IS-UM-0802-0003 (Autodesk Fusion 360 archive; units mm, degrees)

design "IS-UM-0802-0003" references "3M Screw", "6 holes POWER", "8 ports ethernet v2", "Digitus_DN-651107_LAN-Switch", "SFP SLOT", "LED"
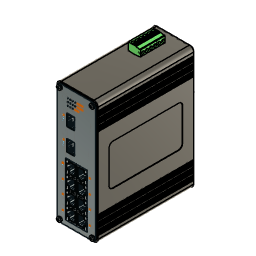
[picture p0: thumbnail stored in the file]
sketch "Sketch1" plane through (0, 0, 0) normal (0, 1, 0) x axis (1, 0, 0)
  line L1 (45, 0) -> (5, 0)
  line L2 (50, -145) -> (50, -5)
  line L3 (5, -150) -> (45, -150)
  line L4 (0, -5) -> (0, -145)
  arc A1 centre (5, -145) radius 5 clockwise from (5, -150) to (0, -145)
  arc A2 centre (45, -145) radius 5 clockwise from (50, -145) to (45, -150)
  arc A3 centre (5, -5) radius 5 clockwise from (0, -5) to (5, 0)
  arc A4 centre (45, -5) radius 5 clockwise from (45, 0) to (50, -5)
  point P1 (0, 0)
  point P2 (0, 0)
  point P4 (0, -150)
  point P3 (50, 0)
  horizontal L1
  vertical L2
  horizontal L3
  vertical L4
  coincident P1 P2
  coincident P4 L3
  coincident P4 L4
  tangent L3 A1
  tangent L4 A1
  tangent L2 A2
  tangent L3 A2
  equal A1 A2
  coincident P2 L1
  coincident P2 L4
  tangent L1 A3
  tangent L4 A3
  equal A1 A3
  coincident P3 L1
  coincident P3 L2
  tangent L1 A4
  tangent L2 A4
  equal A1 A4
  dimension "d1" distance P2 P3 = 50
  dimension "d2" distance P2 P4 = 150
  dimension "d3" radius A1 = 5
extrude "Extrude1" new body sketch "Sketch1" along normal blind 120
sketch "Sketch2" plane through (0, 0, 0) normal (0, -1, 0) x axis (1, 0, 0)
  line L1 (5, 150) -> (45, 150)
  line L2 (0, 5) -> (0, 145)
  line L3 (45, 0) -> (5, 0)
  line L4 (50, 145) -> (50, 5)
  line L5 (45, 1.5) -> (5, 1.5)
  line L6 (48.5, 145) -> (48.5, 5)
  line L7 (5, 148.5) -> (45, 148.5)
  line L8 (1.5, 5) -> (1.5, 145)
  line L9 (45, 0) -> (5, 0)
  line L10 (50, 145) -> (50, 5)
  line L11 (5, 150) -> (45, 150)
  line L12 (0, 5) -> (0, 145)
  arc A1 centre (45, 145) radius 5 clockwise from (45, 150) to (50, 145)
  arc A2 centre (5, 145) radius 5 clockwise from (0, 145) to (5, 150)
  arc A3 centre (5, 5) radius 5 clockwise from (5, 0) to (0, 5)
  arc A4 centre (45, 5) radius 5 clockwise from (50, 5) to (45, 0)
  arc A5 centre (45, 5) radius 3.5 clockwise from (48.5, 5) to (45, 1.5)
  arc A6 centre (45, 145) radius 3.5 clockwise from (45, 148.5) to (48.5, 145)
  arc A7 centre (5, 145) radius 3.5 clockwise from (1.5, 145) to (5, 148.5)
  arc A8 centre (5, 5) radius 3.5 clockwise from (5, 1.5) to (1.5, 5)
  arc A9 centre (45, 5) radius 5 clockwise from (50, 5) to (45, 0)
  arc A10 centre (45, 145) radius 5 clockwise from (45, 150) to (50, 145)
  arc A11 centre (5, 145) radius 5 clockwise from (0, 145) to (5, 150)
  arc A12 centre (5, 5) radius 5 clockwise from (5, 0) to (0, 5)
  dimension "d6" = -1.5
  dimension "d7" distance L3 = 0
extrude "Extrude2" cut sketch "Sketch2" against normal blind 1.5
sketch "Sketch3" plane through (0, 120, 0) normal (0, 1, 0) x axis (-1, 0, 0)
  line L1 (-50, 5) -> (-50, 145)
  line L2 (-5, 0) -> (-45, 0)
  line L3 (0, 145) -> (0, 5)
  line L4 (-45, 150) -> (-5, 150)
  line L5 (-5, 1.5) -> (-45, 1.5)
  line L6 (-1.5, 145) -> (-1.5, 5)
  line L7 (-45, 148.5) -> (-5, 148.5)
  line L8 (-48.5, 5) -> (-48.5, 145)
  line L9 (-5, 0) -> (-45, 0)
  line L10 (0, 145) -> (0, 5)
  line L11 (-45, 150) -> (-5, 150)
  line L12 (-50, 5) -> (-50, 145)
  arc A1 centre (-45, 145) radius 5 clockwise from (-50, 145) to (-45, 150)
  arc A2 centre (-45, 5) radius 5 clockwise from (-45, 0) to (-50, 5)
  arc A3 centre (-5, 5) radius 5 clockwise from (0, 5) to (-5, 0)
  arc A4 centre (-5, 145) radius 5 clockwise from (-5, 150) to (0, 145)
  arc A5 centre (-5, 5) radius 3.5 clockwise from (-1.5, 5) to (-5, 1.5)
  arc A6 centre (-5, 145) radius 3.5 clockwise from (-5, 148.5) to (-1.5, 145)
  arc A7 centre (-45, 145) radius 3.5 clockwise from (-48.5, 145) to (-45, 148.5)
  arc A8 centre (-45, 5) radius 3.5 clockwise from (-45, 1.5) to (-48.5, 5)
  arc A9 centre (-5, 5) radius 5 clockwise from (0, 5) to (-5, 0)
  arc A10 centre (-5, 145) radius 5 clockwise from (-5, 150) to (0, 145)
  arc A11 centre (-45, 145) radius 5 clockwise from (-50, 145) to (-45, 150)
  arc A12 centre (-45, 5) radius 5 clockwise from (-45, 0) to (-50, 5)
  dimension "d10" = -1.5
  dimension "d11" distance L2 = 0
extrude "Extrude3" cut sketch "Sketch3" against normal blind 1.5
sketch "Sketch4" plane through (0, 1.5, 0) normal (0, -1, 0) x axis (1, 0, 0)
  line L1 (1.5, 145) -> (1.5, 5)
  line L2 (45, 148.5) -> (5, 148.5)
  line L3 (48.5, 5) -> (48.5, 145)
  line L4 (5, 1.5) -> (45, 1.5)
  line L5 (45, 0) -> (5, 0)
  line L6 (50, 145) -> (50, 5)
  line L7 (5, 150) -> (45, 150)
  line L8 (0, 5) -> (0, 145)
  line L9 (25, 75) -> (25, 148.5)
  line L10 (25, 75) -> (1.5, 75)
  line L11 (0.75, 9) -> (0, 9)
  line L12 (0.75, 10.5) -> (0.75, 9)
  line L13 (0, 10.5) -> (0.75, 10.5)
  line L14 (0, 9) -> (0, 10.5)
  line L15 (0, 12.75) -> (0.75, 12.75)
  line L16 (0, 11.25) -> (0, 12.75)
  line L17 (0.75, 11.25) -> (0, 11.25)
  line L18 (0.75, 12.75) -> (0.75, 11.25)
  line L19 (0, 15) -> (0.75, 15)
  line L20 (0, 13.5) -> (0, 15)
  line L21 (0.75, 13.5) -> (0, 13.5)
  line L22 (0.75, 15) -> (0.75, 13.5)
  line L23 (0.75, 19.25) -> (0, 19.25)
  line L24 (0.75, 20.75) -> (0.75, 19.25)
  line L25 (0, 19.25) -> (0, 20.75)
  line L26 (0.75, 18.5) -> (0.75, 17)
  line L27 (0, 21.5) -> (0, 23)
  line L28 (0, 23) -> (0.75, 23)
  line L29 (0.75, 21.5) -> (0, 21.5)
  line L30 (0, 20.75) -> (0.75, 20.75)
  line L31 (0, 18.5) -> (0.75, 18.5)
  line L32 (0, 17) -> (0, 18.5)
  line L33 (0.75, 17) -> (0, 17)
  line L34 (0.75, 23) -> (0.75, 21.5)
  line L35 (0.75, 27.25) -> (0, 27.25)
  line L36 (0.75, 28.75) -> (0.75, 27.25)
  line L37 (0, 27.25) -> (0, 28.75)
  line L38 (0.75, 26.5) -> (0.75, 25)
  line L39 (0, 29.5) -> (0, 31)
  line L40 (0, 31) -> (0.75, 31)
  line L41 (0.75, 29.5) -> (0, 29.5)
  line L42 (0, 28.75) -> (0.75, 28.75)
  line L43 (0, 26.5) -> (0.75, 26.5)
  line L44 (0, 25) -> (0, 26.5)
  line L45 (0.75, 25) -> (0, 25)
  line L46 (0.75, 31) -> (0.75, 29.5)
  line L47 (0.75, 141) -> (0, 141)
  line L48 (0, 138.75) -> (0, 137.25)
  line L49 (0, 133) -> (0, 131.5)
  line L50 (0, 120.5) -> (0, 119)
  line L51 (0, 128.5) -> (0, 127)
  line L52 (0, 121.25) -> (0.75, 121.25)
  line L53 (0.75, 125) -> (0, 125)
  line L54 (0.75, 128.5) -> (0, 128.5)
  line L55 (0.75, 129.25) -> (0.75, 130.75)
  line L56 (0.75, 120.5) -> (0, 120.5)
  line L57 (0.75, 131.5) -> (0.75, 133)
  line L58 (0.75, 123.5) -> (0.75, 125)
  line L59 (0, 122.75) -> (0, 121.25)
  line L60 (0.75, 138.75) -> (0, 138.75)
  line L61 (0, 130.75) -> (0, 129.25)
  line L62 (0.75, 130.75) -> (0, 130.75)
  line L63 (0, 139.5) -> (0.75, 139.5)
  line L64 (0.75, 133) -> (0, 133)
  line L65 (0.75, 127) -> (0.75, 128.5)
  line L66 (0.75, 137.25) -> (0.75, 138.75)
  line L67 (0, 137.25) -> (0.75, 137.25)
  line L68 (0.75, 119) -> (0.75, 120.5)
  line L69 (0, 125) -> (0, 123.5)
  line L70 (0.75, 122.75) -> (0, 122.75)
  line L71 (0.75, 139.5) -> (0.75, 141)
  line L72 (0, 129.25) -> (0.75, 129.25)
  line L73 (0, 123.5) -> (0.75, 123.5)
  line L74 (0, 119) -> (0.75, 119)
  line L75 (0, 141) -> (0, 139.5)
  line L76 (0.75, 135) -> (0.75, 136.5)
  line L77 (0.75, 136.5) -> (0, 136.5)
  line L78 (0, 136.5) -> (0, 135)
  line L79 (0, 131.5) -> (0.75, 131.5)
  line L80 (0, 135) -> (0.75, 135)
  line L81 (0.75, 121.25) -> (0.75, 122.75)
  line L82 (0, 127) -> (0.75, 127)
  line L83 (49.25, 127) -> (49.25, 128.5)
  line L84 (50, 122.75) -> (50, 121.25)
  line L85 (49.25, 121.25) -> (49.25, 122.75)
  line L86 (50, 127) -> (49.25, 127)
  line L87 (49.25, 129.25) -> (49.25, 130.75)
  line L88 (49.25, 137.25) -> (49.25, 138.75)
  line L89 (50, 119) -> (49.25, 119)
  line L90 (50, 139.5) -> (49.25, 139.5)
  line L91 (50, 123.5) -> (49.25, 123.5)
  line L92 (50, 136.5) -> (50, 135)
  line L93 (50, 135) -> (49.25, 135)
  line L94 (50, 120.5) -> (50, 119)
  line L95 (50, 133) -> (50, 131.5)
  line L96 (49.25, 119) -> (49.25, 120.5)
  line L97 (50, 128.5) -> (50, 127)
  line L98 (49.25, 131.5) -> (49.25, 133)
  line L99 (49.25, 120.5) -> (50, 120.5)
  line L100 (49.25, 133) -> (50, 133)
  line L101 (50, 138.75) -> (50, 137.25)
  line L102 (50, 125) -> (50, 123.5)
  line L103 (49.25, 139.5) -> (49.25, 141)
  line L104 (49.25, 135) -> (49.25, 136.5)
  line L105 (49.25, 136.5) -> (50, 136.5)
  line L106 (50, 137.25) -> (49.25, 137.25)
  line L107 (49.25, 125) -> (50, 125)
  line L108 (50, 121.25) -> (49.25, 121.25)
  line L109 (49.25, 138.75) -> (50, 138.75)
  line L110 (50, 130.75) -> (50, 129.25)
  line L111 (49.25, 141) -> (50, 141)
  line L112 (49.25, 130.75) -> (50, 130.75)
  line L113 (50, 129.25) -> (49.25, 129.25)
  line L114 (50, 131.5) -> (49.25, 131.5)
  line L115 (49.25, 122.75) -> (50, 122.75)
  line L116 (50, 141) -> (50, 139.5)
  line L117 (49.25, 128.5) -> (50, 128.5)
  line L118 (49.25, 123.5) -> (49.25, 125)
  line L119 (50, 18.5) -> (49.25, 18.5)
  line L120 (49.25, 19.25) -> (50, 19.25)
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  point P22 (25, 148.5)
  point P23 (1.5, 75)
  point P25 (0, 9)
  point P74 (0, 141)
  point P26 (0.75, 9)
  point P81 (0.75, 141)
  point P27 (0.75, 10.5)
  point P77 (0.75, 139.5)
  point P28 (0, 10.5)
  point P69 (0, 139.5)
  point P29 (0.75, 12.75)
  point P67 (0.75, 137.25)
  point P30 (0, 12.75)
  point P68 (0, 137.25)
  point P31 (0, 11.25)
  point P89 (0, 138.75)
  point P32 (0.75, 11.25)
  point P86 (0.75, 138.75)
  point P33 (0.75, 15)
  point P79 (0.75, 135)
  point P34 (0, 15)
  point P94 (0, 135)
  point P35 (0, 13.5)
  point P90 (0, 136.5)
  point P36 (0.75, 13.5)
  point P65 (0.75, 136.5)
  point P37 (0.75, 17)
  point P95 (0.75, 133)
  point P38 (0, 19.25)
  point P96 (0, 130.75)
  point P39 (0.75, 19.25)
  point P75 (0.75, 130.75)
  point P40 (0.75, 20.75)
  point P72 (0.75, 129.25)
  point P41 (0.75, 23)
  point P73 (0.75, 127)
  point P42 (0, 20.75)
  point P62 (0, 129.25)
  point P43 (0, 23)
  point P61 (0, 127)
  point P44 (0.75, 18.5)
  point P63 (0.75, 131.5)
  point P45 (0, 21.5)
  point P66 (0, 128.5)
  point P46 (0, 17)
  point P70 (0, 133)
  point P47 (0.75, 21.5)
  point P91 (0.75, 128.5)
  point P48 (0, 18.5)
  point P84 (0, 131.5)
  point P49 (0.75, 25)
  point P83 (0.75, 125)
  point P50 (0, 27.25)
  point P76 (0, 122.75)
  point P51 (0.75, 27.25)
  point P78 (0.75, 122.75)
  point P52 (0.75, 28.75)
  point P88 (0.75, 121.25)
  point P53 (0.75, 31)
  point P87 (0.75, 119)
  point P54 (0, 28.75)
  point P82 (0, 121.25)
  point P55 (0, 31)
  point P80 (0, 119)
  point P56 (0.75, 26.5)
  point P85 (0.75, 123.5)
  point P57 (0, 29.5)
  point P93 (0, 120.5)
  point P58 (0, 25)
  point P92 (0, 125)
  point P59 (0.75, 29.5)
  point P71 (0.75, 120.5)
  point P60 (0, 26.5)
  point P64 (0, 123.5)
  point P5 (1.5, 145)
  point P123 (48.5, 145)
  point P21 (0, 145)
  point P106 (50, 145)
  point P145 (50, 9)
  point P140 (49.25, 9)
  point P158 (49.25, 10.5)
  point P153 (50, 10.5)
  point P166 (49.25, 12.75)
  point P170 (50, 12.75)
  point P169 (50, 11.25)
  point P167 (49.25, 11.25)
  point P151 (49.25, 15)
  point P152 (50, 15)
  point P154 (50, 13.5)
  point P161 (49.25, 13.5)
  point P143 (49.25, 17)
  point P141 (50, 19.25)
  point P137 (49.25, 19.25)
  point P160 (49.25, 20.75)
  point P155 (49.25, 23)
  point P156 (50, 20.75)
  point P162 (50, 23)
  point P159 (49.25, 18.5)
  point P148 (50, 21.5)
  point P149 (50, 17)
  point P147 (49.25, 21.5)
  point P165 (50, 18.5)
  point P168 (49.25, 25)
  point P150 (50, 27.25)
  point P157 (49.25, 27.25)
  point P163 (49.25, 28.75)
  point P164 (49.25, 31)
  point P144 (50, 28.75)
  point P136 (50, 31)
  point P146 (49.25, 26.5)
  point P139 (50, 29.5)
  point P142 (50, 25)
  point P138 (49.25, 29.5)
  point P135 (50, 26.5)
  point P97 (50, 127)
  point P100 (50, 129.25)
  point P98 (49.25, 131.5)
  point P99 (50, 123.5)
  point P105 (49.25, 136.5)
  point P114 (50, 128.5)
  point P103 (49.25, 137.25)
  point P102 (50, 137.25)
  point P101 (50, 139.5)
  point P110 (50, 133)
  point P115 (49.25, 120.5)
  point P111 (49.25, 129.25)
  point P112 (49.25, 127)
  point P104 (50, 141)
  point P113 (49.25, 130.75)
  point P132 (50, 122.75)
  point P109 (49.25, 139.5)
  point P131 (49.25, 122.75)
  point P108 (49.25, 135)
  point P134 (50, 119)
  point P117 (49.25, 141)
  point P133 (50, 121.25)
  point P130 (49.25, 125)
  point P124 (50, 131.5)
  point P125 (49.25, 123.5)
  point P121 (49.25, 138.75)
  point P127 (49.25, 119)
  point P128 (49.25, 121.25)
  point P118 (50, 138.75)
  point P120 (50, 136.5)
  point P122 (49.25, 128.5)
  point P119 (50, 125)
  point P116 (50, 120.5)
  point P126 (50, 135)
  point P107 (49.25, 133)
  point P129 (50, 130.75)
  midpoint L2 P22
  perpendicular L2 L9
  midpoint L1 P23
  perpendicular L9 L10
  horizontal L11
  vertical L12
  horizontal L13
  vertical L14
  coincident L8 P25
  symmetric L10 P25 P74
  symmetric L10 P26 P81
  symmetric L10 P27 P77
  symmetric L10 P28 P69
  symmetric L10 P29 P67
  symmetric L10 P30 P68
  symmetric L10 P31 P89
  symmetric L10 P32 P86
  symmetric L10 P33 P79
  symmetric L10 P34 P94
  symmetric L10 P35 P90
  symmetric L10 P36 P65
  symmetric L10 P37 P95
  symmetric L10 P38 P96
  symmetric L10 P39 P75
  symmetric L10 P40 P72
  symmetric L10 P41 P73
  symmetric L10 P42 P62
  symmetric L10 P43 P61
  symmetric L10 P44 P63
  symmetric L10 P45 P66
  symmetric L10 P46 P70
  symmetric L10 P47 P91
  symmetric L10 P48 P84
  symmetric L10 P49 P83
  symmetric L10 P50 P76
  symmetric L10 P51 P78
  symmetric L10 P52 P88
  symmetric L10 P53 P87
  symmetric L10 P54 P82
  symmetric L10 P55 P80
  symmetric L10 P56 P85
  symmetric L10 P57 P93
  symmetric L10 P58 P92
  symmetric L10 P59 P71
  symmetric L10 P60 P64
  symmetric P5 L9 P123
  symmetric P21 L9 P106
  symmetric L9 P25 P145
  symmetric L9 P26 P140
  symmetric L9 P27 P158
  symmetric L9 P28 P153
  symmetric L9 P29 P166
  symmetric L9 P30 P170
  symmetric L9 P31 P169
  symmetric L9 P32 P167
  symmetric L9 P33 P151
  symmetric L9 P34 P152
  symmetric L9 P35 P154
  symmetric L9 P36 P161
  symmetric L9 P37 P143
  symmetric L9 P38 P141
  symmetric L9 P39 P137
  symmetric L9 P40 P160
  symmetric L9 P41 P155
  symmetric L9 P42 P156
  symmetric L9 P43 P162
  symmetric L9 P44 P159
  symmetric L9 P45 P148
  symmetric L9 P46 P149
  symmetric L9 P47 P147
  symmetric L9 P48 P165
  symmetric L9 P49 P168
  symmetric L9 P50 P150
  symmetric L9 P51 P157
  symmetric L9 P52 P163
  symmetric L9 P53 P164
  symmetric L9 P54 P144
  symmetric L9 P55 P136
  symmetric L9 P56 P146
  symmetric L9 P57 P139
  symmetric L9 P58 P142
  symmetric L9 P59 P138
  symmetric L9 P60 P135
  symmetric L9 P61 P97
  symmetric L9 P62 P100
  symmetric L9 P63 P98
  symmetric L9 P64 P99
  symmetric L9 P65 P105
  symmetric L9 P66 P114
  symmetric L9 P67 P103
  symmetric L9 P68 P102
  symmetric L9 P69 P101
  symmetric L9 P70 P110
  symmetric L9 P71 P115
  symmetric L9 P72 P111
  symmetric L9 P73 P112
  symmetric L9 P74 P104
  symmetric L9 P75 P113
  symmetric L9 P76 P132
  symmetric L9 P77 P109
  symmetric L9 P78 P131
  symmetric L9 P79 P108
  symmetric L9 P80 P134
  symmetric L9 P81 P117
  symmetric L9 P82 P133
  symmetric L9 P83 P130
  symmetric L9 P84 P124
  symmetric L9 P85 P125
  symmetric L9 P86 P121
  symmetric L9 P87 P127
  symmetric L9 P88 P128
  symmetric L9 P89 P118
  symmetric L9 P90 P120
  symmetric L9 P91 P122
  symmetric L9 P92 P119
  symmetric L9 P93 P116
  symmetric L9 P94 P126
  symmetric L9 P95 P107
  symmetric L9 P96 P129
  dimension "d14" distance P25 P28 = 1.5
  dimension "d15" distance P27 P28 = 0.75
  dimension "d24" distance L10 L40 = 44
  dimension "d18" R-Pattern1-uDistance = 0
  dimension "d19" R-Pattern1-vDistance = 4.5
  dimension "d22" R-Pattern2-uDistance = 0
  dimension "d23" R-Pattern2-vDistance = 16
extrude "Extrude4" cut sketch "Sketch4" against normal blind 125
sketch "Sketch10" plane through (0, 0, 0) normal (0, -1, 0) x axis (1, 0, 0)
  line L1 (1.5, 5) -> (1.5, 145)
  line L2 (45, 1.5) -> (5, 1.5)
  line L3 (48.5, 145) -> (48.5, 5)
  line L4 (5, 148.5) -> (45, 148.5)
  line L5 (25, 75) -> (25, 148.5)
  line L6 (25, 75) -> (1.5, 75)
  line L7 (22.04, 80) -> (13.84, 80)
  line L8 (22.79, 93.75) -> (22.79, 80.75)
  line L9 (13.84, 94.5) -> (22.04, 94.5)
  line L10 (13.09, 80.75) -> (13.09, 93.75)
  line L11 (13.84, 121.5) -> (22.04, 121.5)
  line L12 (13.09, 107.75) -> (13.09, 120.75)
  line L13 (22.79, 120.75) -> (22.79, 107.75)
  line L14 (22.04, 107) -> (13.84, 107)
  line L15 (11.84, 7.39) -> (38.16, 7.39)
  line L16 (11.84, 73) -> (11.84, 7.39)
  line L17 (38.16, 73) -> (11.84, 73)
  line L18 (38.16, 7.39) -> (38.16, 73)
  arc A1 centre (5, 5) radius 3.5 clockwise from (5, 1.5) to (1.5, 5)
  arc A2 centre (45, 5) radius 3.5 clockwise from (48.5, 5) to (45, 1.5)
  arc A3 centre (45, 145) radius 3.5 clockwise from (45, 148.5) to (48.5, 145)
  arc A4 centre (5, 145) radius 3.5 clockwise from (1.5, 145) to (5, 148.5)
  arc A5 centre (13.84, 80.75) radius 0.75 clockwise from (13.84, 80) to (13.09, 80.75)
  arc A6 centre (22.04, 80.75) radius 0.75 clockwise from (22.79, 80.75) to (22.04, 80)
  arc A7 centre (22.04, 93.75) radius 0.75 clockwise from (22.04, 94.5) to (22.79, 93.75)
  arc A8 centre (13.84, 93.75) radius 0.75 clockwise from (13.09, 93.75) to (13.84, 94.5)
  arc A9 centre (22.04, 120.75) radius 0.75 clockwise from (22.04, 121.5) to (22.79, 120.75)
  arc A10 centre (13.84, 120.75) radius 0.75 clockwise from (13.09, 120.75) to (13.84, 121.5)
  arc A11 centre (13.84, 107.75) radius 0.75 clockwise from (13.84, 107) to (13.09, 107.75)
  arc A12 centre (22.04, 107.75) radius 0.75 clockwise from (22.79, 107.75) to (22.04, 107)
  circle C1 centre (14.59, 129.5) radius 0.75
  circle C2 centre (17.59, 129.5) radius 0.75
  circle C3 centre (20.59, 129.5) radius 0.75
  circle C4 centre (14.59, 133.5) radius 0.75
  circle C5 centre (17.59, 133.5) radius 0.75
  circle C6 centre (20.59, 133.5) radius 0.75
  circle C7 centre (14.59, 137.5) radius 0.75
  circle C8 centre (17.59, 137.5) radius 0.75
  circle C9 centre (20.59, 137.5) radius 0.75
  circle C10 centre (23.59, 137.5) radius 0.75
  circle C11 centre (23.59, 133.5) radius 0.75
  circle C12 centre (5, 145) radius 1.5
  circle C13 centre (45, 145) radius 1.5
  circle C14 centre (5, 5) radius 1.5
  circle C15 centre (45, 5) radius 1.5
  point P14 (25, 148.5)
  point P15 (1.5, 75)
  point P17 (13.09, 80)
  point P18 (22.79, 94.5)
  point P19 (13.09, 94.5)
  point P44 (14.59, 129.5)
  point P59 (38.16, 7.39)
  point P60 (11.84, 7.39)
  point P62 (38.16, 73)
  midpoint L4 P14
  perpendicular L4 L5
  midpoint L1 P15
  perpendicular L5 L6
  horizontal L7
  vertical L8
  horizontal L9
  vertical L10
  coincident P17 L7
  coincident P17 L10
  tangent L7 A5
  tangent L10 A5
  tangent L7 A6
  tangent L8 A6
  equal A5 A6
  coincident P18 L8
  coincident P18 L9
  tangent L8 A7
  tangent L9 A7
  equal A5 A7
  coincident P19 L9
  coincident P19 L10
  tangent L9 A8
  tangent L10 A8
  equal A5 A8
  concentric A4 C12
  horizontal L15
  vertical L16
  horizontal L17
  vertical L18
  symmetric L5 L16 L18
  dimension "d145" distance P17 P19 = 14.5
  dimension "d146" distance P18 P19 = 9.7
  dimension "d147" radius A5 = 0.75
  dimension "d148" distance L6 L7 = 5
  dimension "d154" diameter C1 = 1.5
  dimension "d155" distance L11 P44 = 8
  dimension "d156" distance L12 P44 = 1.5
  dimension "d169" diameter C12 = 3
  dimension "d228" distance P59 P60 = 26.32
  dimension "d229" distance P59 P62 = 65.61
  dimension "d230" distance L6 L17 = 2
  dimension "d152" R-Pattern1-uDistance = 0
  dimension "d153" R-Pattern1-vDistance = 27
  dimension "d159" R-Pattern2-uDistance = 6
  dimension "d160" R-Pattern2-vDistance = 0
  dimension "d163" R-Pattern3-uDistance = 0
  dimension "d164" R-Pattern3-vDistance = 8
  dimension "d167" R-Pattern4-uDistance = 3
  dimension "d168" R-Pattern4-vDistance = 0
  dimension "d172" R-Pattern5-uDistance = 40
  dimension "d173" R-Pattern5-vDistance = 0
  dimension "d176" R-Pattern6-uDistance = 0
  dimension "d177" R-Pattern6-vDistance = -140
extrude "Extrude8" cut sketch "Sketch10" profile of L7 L8 L9 L10 A5 A6 A7 A8 L11 A9 A10 L12 L13 A11 L14 A12 C1 C2 C3 C4 C5 C6 C7 C8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 against normal blind 3
shell "Shell3" innerThickness 1
sketch "Sketch11" plane through (0, 0, 150) normal (0, 0, 1) x axis (-1, 0, 0)
  line L1 (-5, -118.5) -> (-45, -118.5)
  line L2 (-5, -1.5) -> (-5, -118.5)
  line L3 (-45, -1.5) -> (-5, -1.5)
  line L4 (-45, -118.5) -> (-45, -1.5)
  line L5 (-25, -60) -> (-25, -118.5)
  line L6 (-25, -60) -> (-5, -60)
  line L7 (-22, -105) -> (-13.4, -105)
  line L8 (-22, -75) -> (-22, -105)
  line L9 (-13.4, -75) -> (-22, -75)
  line L10 (-13.4, -105) -> (-13.4, -75)
  point P6 (-25, -118.5)
  point P7 (-5, -60)
  point P9 (-13.4, -105)
  point P12 (-13.4, -75)
  point P10 (-22, -105)
  midpoint L1 P6
  perpendicular L1 L5
  midpoint L2 P7
  perpendicular L2 L6
  horizontal L7
  vertical L8
  horizontal L9
  vertical L10
  dimension "d181" distance P9 P12 = 30
  dimension "d182" distance P9 P10 = 8.6
  dimension "d183" distance L5 L8 = 3
  dimension "d184" distance L6 L9 = 15
extrude "Extrude9" cut sketch "Sketch11" profile of L7 L8 L9 L10 against normal blind 5
component_insert "Component Insert1"
joint "Assemble3" alignAngle 0 alignOffsetX 0 alignOffsetY 0 alignOffsetZ 2.5
rectangular_pattern "00000000-0000-0000-0000-000000000000" uSpaceDistance 6 vSpaceDistance 0
rectangular_pattern "00000000-0000-0000-0000-000000000000" uSpaceDistance 8 vSpaceDistance 0
rectangular_pattern "00000000-0000-0000-0000-000000000000" uSpaceDistance 3 vSpaceDistance 0
component_insert "Component Insert4"
joint "Assemble4" alignAngle -90 alignOffsetX 0 alignOffsetY 0 alignOffsetZ 6
rectangular_pattern "00000000-0000-0000-0000-000000000000" uSpaceDistance 40 vSpaceDistance 0
rectangular_pattern "00000000-0000-0000-0000-000000000000" uSpaceDistance -140 vSpaceDistance 0
component_insert "Component Insert7"
position "Position2"
component_insert "Component Insert10"
decal "Decal1"
sketch "Sketch9" plane through (50, 0, 0) normal (1, 0, 0) x axis (0, 1, 0)
  line L1 (118.5, 31) -> (1.5, 31)
  line L2 (118.5, 119) -> (118.5, 31)
  line L3 (1.5, 119) -> (118.5, 119)
  line L4 (1.5, 31) -> (1.5, 119)
  line L5 (60, 75) -> (60, 119)
  line L6 (60, 75) -> (1.5, 75)
  line L7 (100, 100) -> (20, 100)
  line L8 (105, 55) -> (105, 95)
  line L9 (20, 50) -> (100, 50)
  line L10 (15, 95) -> (15, 55)
  arc A1 centre (20, 55) radius 5 clockwise from (20, 50) to (15, 55)
  arc A2 centre (100, 55) radius 5 clockwise from (105, 55) to (100, 50)
  arc A3 centre (100, 95) radius 5 clockwise from (100, 100) to (105, 95)
  arc A4 centre (20, 95) radius 5 clockwise from (15, 95) to (20, 100)
  point P6 (60, 119)
  point P7 (1.5, 75)
  point P11 (15, 50)
  point P10 (105, 50)
  point P9 (15, 100)
  midpoint L3 P6
  perpendicular L3 L5
  midpoint L4 P7
  perpendicular L4 L6
  horizontal L7
  vertical L8
  horizontal L9
  vertical L10
  symmetric L6 L7 L9
  coincident P11 L9
  coincident P11 L10
  tangent L9 A1
  tangent L10 A1
  coincident P10 L8
  coincident P10 L9
  tangent L8 A2
  tangent L9 A2
  equal A1 A2
  tangent L7 A3
  tangent L8 A3
  equal A1 A3
  coincident P9 L7
  coincident P9 L10
  tangent L7 A4
  tangent L10 A4
  equal A1 A4
  dimension "d137" distance P9 P11 = 50
  dimension "d138" distance P10 P11 = 90
  dimension "d139" radius A1 = 5
extrude "Extrude7" cut sketch "Sketch9" profile of L5 L6 L7 L8 L9 L10 A1 A2 A3 A4 against normal blind 0.5
component_insert "Component Insert11"
position "Position4"
rectangular_pattern "00000000-0000-0000-0000-000000000000" uSpaceDistance -27 vSpaceDistance 0
component_insert "Component Insert14"
position "Position6"
sketch "Sketch13" plane through (0, 0, 0) normal (0, -1, 0) x axis (1, 0, 0)
  dimension "d232" = 2
  dimension "d234" = 2
  dimension "d235" = 2
  dimension "d236" = 2
  dimension "d237" = 2
  dimension "d238" = 2
  dimension "d239" = 2
  dimension "d240" = 2
  dimension "d241" = 2
  dimension "d242" = 2
  dimension "d243" = 2
  dimension "d244" = 1
  dimension "d245" = 1
  dimension "d246" = 1
  dimension "d247" = 1
  dimension "d249" = 1
  dimension "d251" = 1
  dimension "d252" = 1
  dimension "d254" = 1
  dimension "d255" = 1
  dimension "d256" = 1
  dimension "d257" = 1
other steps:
joint_origin "JointOrigin3"
joint_origin "JointOrigin4"

design "LED"
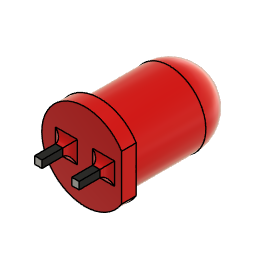
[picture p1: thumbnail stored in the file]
description: STEP AP214
part number: LED

design "6 holes POWER"
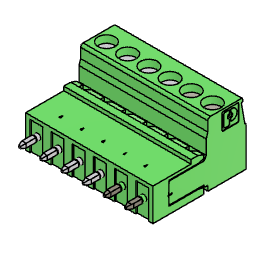
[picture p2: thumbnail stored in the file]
description: STEP AP214
part number: POWER

design "3M Screw"
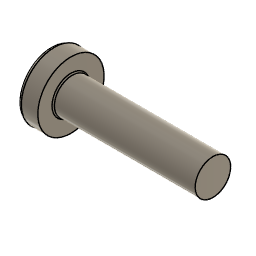
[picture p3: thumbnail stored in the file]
description: STEP AP214
part number: 3M Screw

design "SFP SLOT"
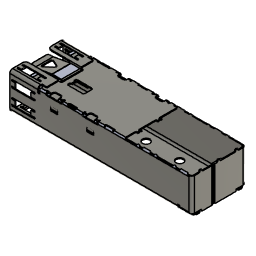
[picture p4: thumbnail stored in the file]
description: STEP AP214
part number: SFP SLOT

design "8 ports ethernet v2"
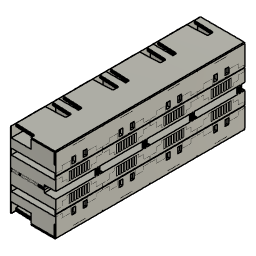
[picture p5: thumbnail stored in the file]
description: STEP AP214
part number: 8 ports ethernet

design "Digitus_DN-651107_LAN-Switch"
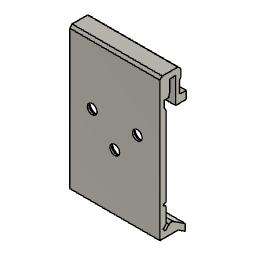
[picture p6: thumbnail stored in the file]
description: STEP AP214
part number: Digitus_DN-651107_LAN-Switch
